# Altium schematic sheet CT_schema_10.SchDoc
size 274 x 160 mm
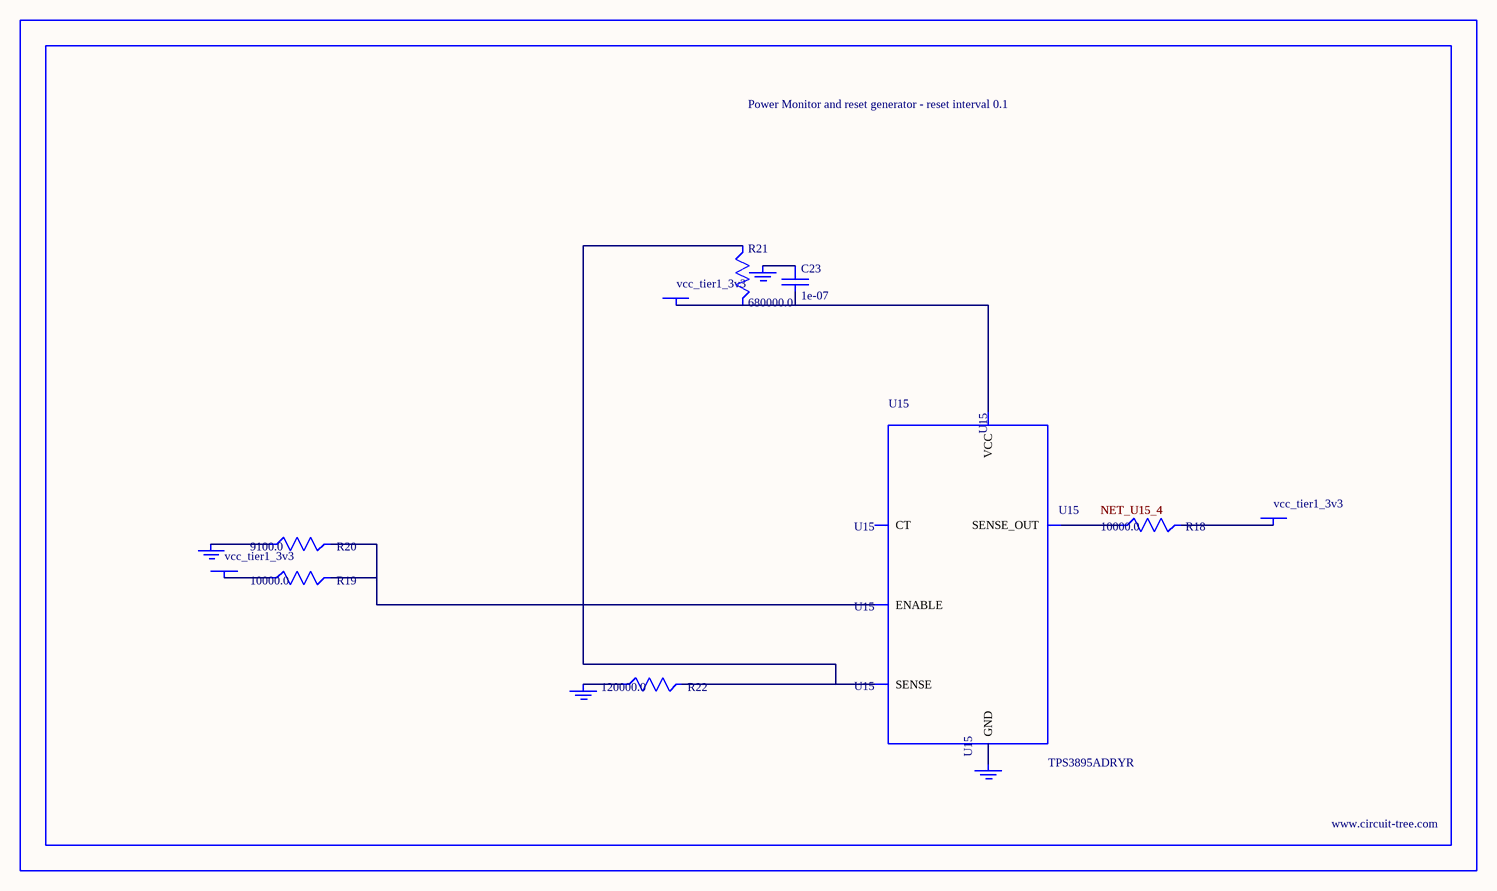
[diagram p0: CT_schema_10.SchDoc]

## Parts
BORDER9  (no value)
C23  1e-07  [C0402]
GND_INSTANCE_9_0  (no value)
GND_INSTANCE_9_1  (no value)
GND_INSTANCE_9_2  (no value)
GND_INSTANCE_9_3  (no value)
POWER_INSTANCE_9_0  vcc_tier1_3v3
POWER_INSTANCE_9_1  vcc_tier1_3v3
POWER_INSTANCE_9_2  vcc_tier1_3v3
R18  10000.0  [R0603]
R19  10000.0  [R0603]
R20  9100.0  [R0603]
R21  680000.0  [R0603]
R22  120000.0  [R0603]
U15  TPS3895ADRYR  [SON-6]

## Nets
NetC23_1: C23.1 GND_INSTANCE_9_2.0(GND)
NetC23_2: C23.2 POWER_INSTANCE_9_2.0(PWR) R21.2 U15.6(VCC)
NetGND_INSTANCE_9_0_0: GND_INSTANCE_9_0.0(GND) R20.1
NetGND_INSTANCE_9_1_0: GND_INSTANCE_9_1.0(GND) R22.1
NetGND_INSTANCE_9_3_0: GND_INSTANCE_9_3.0(GND) U15.2(GND)
NetPOWER_INSTANCE_9_0_0: POWER_INSTANCE_9_0.0(PWR) R19.1
NetPOWER_INSTANCE_9_1_0: POWER_INSTANCE_9_1.0(PWR) R18.2
NetR18_1: R18.1 U15.4(SENSE_OUT)
NetR19_2: R19.2 R20.2 U15.1(ENABLE)
NetR21_1: R21.1 R22.2 U15.3(SENSE)

Not connected (* = marked no-connect by the designer): U15 5(CT)

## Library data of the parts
BORDER9 = BORDER_PAGE9
C23 = C0402C104K3RACTU
GND_INSTANCE_9_0-GND_INSTANCE_9_3 = GND
POWER_INSTANCE_9_0-POWER_INSTANCE_9_2 = PWR
R18 R19 = RC0603JR-0710KL
R20 = RC0603JR-079K1L
R21 = RC0603JR-07680KL
R22 = RC0603JR-07120KL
